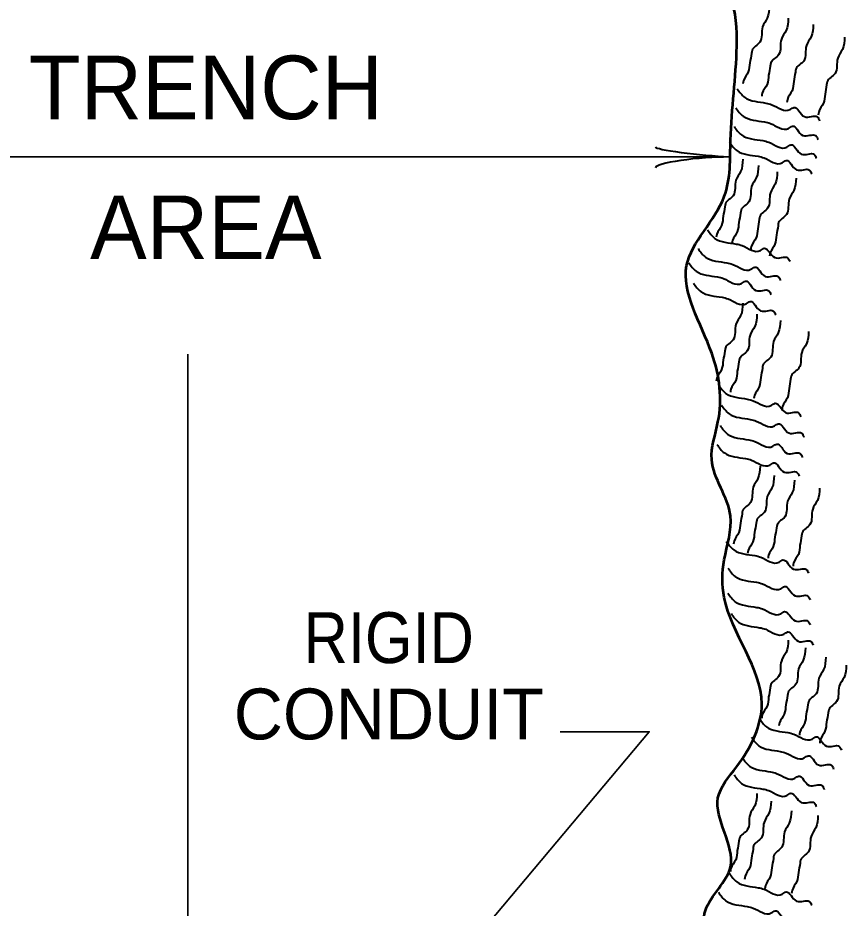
# Model space of a CAD drawing. Extents: x -488 to 193, y 19 to 459.
# Drawn here: x -199.42 to -166.87, y 242.11 to 277.11 of the extents above; entities that cross this region are included whole.
import ezdxf
from ezdxf.enums import TextEntityAlignment as Align

# ---------------------------------------------------------------- set-up
doc = ezdxf.new("R2010")
doc.units = 0
doc.header["$LTSCALE"] = 0.8
doc.layers.add('1', color=7, linetype='Continuous', lineweight=40)

msp = doc.modelspace()

# ---------------------------------------------------------------- linework, layer by layer
at = {"layer": '1', "lineweight": 35}
for p, q in [((-171.4865, 271.6481), (-212.2884, 271.6481)), ((-192.7425, 224.5147), (-192.7425, 263.8855))]:
    msp.add_line(p, q, dxfattribs=at)
msp.add_lwpolyline([(-187.0093, 234.2723), (-174.6099, 249.0493), (-178.1099, 249.0493)], dxfattribs=at)
at = {"layer": '1'}
for centre, major_axis, ratio, start_param, end_param in [((-172.607, 271.8597), (1.7565, -0.1757), 0.07063, 3.1407148, 5.41811), ((-172.5777, 271.3718), (1.7857, 0.1562), 0.122415, 0.8963533, 3.1415927)]:
    msp.add_ellipse(centre, major_axis=major_axis, ratio=ratio, start_param=start_param, end_param=end_param, dxfattribs=at)
at = {"layer": '1', "lineweight": 53}
msp.add_spline([(-212.7425, 318.8428), (-213.2734, 312.6869), (-212.2884, 310.2246), (-213.2734, 308.0085), (-212.5347, 306.0386), (-213.2734, 303.3301), (-212.2884, 301.6064), (-212.0422, 299.3903), (-212.2884, 295.943), (-212.5347, 294.2194), (-213.5196, 292.9882), (-213.7658, 292.2495), (-213.2734, 291.0183), (-213.0272, 289.5409), (-212.7809, 287.8173), (-212.5347, 286.0937), (-212.5347, 284.1237), (-211.5497, 281.4152), (-211.796, 279.6916), (-212.2884, 278.7066), (-212.2884, 275.9981), (-212.0422, 272.797), (-212.2884, 271.5658), (-212.2884, 268.8572), (-212.7809, 265.41), (-212.7809, 262.9477), (-213.7658, 259.7466), (-213.0272, 258.0229), (-213.2734, 255.8068), (-213.5196, 253.0982), (-213.2734, 251.3746), (-213.0272, 248.4198), (-212.7809, 246.6962), (-213.0272, 244.7263), (-213.0272, 241.5252), (-212.2884, 240.7866), (-212.7809, 236.8468), (-212.7809, 234.6307), (-212.5347, 233.1532), (-213.0272, 230.1985), (-212.5347, 228.9673), (-213.0272, 226.7512), (-212.5347, 225.7662), (-210.5648, 223.7964), (-208.8412, 224.2888), (-207.1175, 225.52), (-205.6401, 224.2888), (-204.1627, 224.0426), (-200.9617, 224.0426), (-197.7606, 225.2738), (-196.7757, 224.5351), (-192.5897, 224.5351), (-188.8962, 225.0276), (-186.9263, 224.5351), (-182.7403, 225.0276), (-181.2629, 224.7813), (-176.8307, 225.0276), (-176.3382, 224.2888), (-173.3834, 224.7813), (-171.1673, 227.7362), (-171.4136, 229.4597), (-171.6598, 230.4447), (-173.1372, 235.1232), (-171.1673, 238.3242), (-172.3985, 241.0327), (-172.3985, 242.0177), (-171.4136, 243.7413), (-171.906, 246.4499), (-171.1673, 247.6811), (-170.1824, 250.1434), (-171.6598, 254.3294), (-171.6598, 255.8068), (-171.4136, 257.5305), (-172.1522, 259.7466), (-171.906, 261.224), (-172.1522, 263.9326), (-173.1372, 267.3798), (-171.6598, 270.0884), (-171.4136, 272.3045), (-171.1673, 275.9981), (-171.4136, 277.9679), (-172.1522, 279.6916), (-172.1522, 281.169), (-171.906, 284.1237), (-172.891, 287.0786), (-173.1372, 289.7872), (-171.4136, 292.4957), (-172.1522, 294.4656), (-172.3985, 295.6968), (-171.1673, 298.6516), (-172.1522, 300.8677), (-172.1522, 305.0537), (-171.906, 306.5311), (-171.6598, 308.0085), (-172.6447, 310.7171), (-172.891, 312.1945), (-172.7425, 318.8428)], degree=3, dxfattribs=at)
at = {"layer": '1'}
for points in [[(-169.8844, 277.5847), (-169.9699, 277.0997), (-170.1552, 276.7574), (-170.2622, 276.1511), (-170.5689, 275.8302), (-170.5902, 275.709), (-170.6543, 275.3452), (-170.7184, 274.9814), (-170.9039, 274.6392), (-170.9253, 274.5178)], [(-169.1457, 277.0922), (-169.2312, 276.6073), (-169.4166, 276.265), (-169.5235, 275.6587), (-169.8303, 275.3377), (-169.8515, 275.2166), (-169.9157, 274.8528), (-169.9797, 274.489), (-170.1652, 274.1467), (-170.1867, 274.0254)], [(-168.1608, 276.846), (-168.2463, 276.3611), (-168.4316, 276.0188), (-168.5385, 275.4124), (-168.8452, 275.0915), (-168.8665, 274.9703), (-168.9307, 274.6065), (-168.9947, 274.2428), (-169.1803, 273.9005), (-169.2017, 273.7792)], [(-166.9296, 276.3535), (-167.0151, 275.8686), (-167.2004, 275.5263), (-167.3073, 274.9199), (-167.6141, 274.599), (-167.6353, 274.4778), (-167.6995, 274.114), (-167.7636, 273.7502), (-167.9491, 273.408), (-167.9705, 273.2867)], [(-171.1485, 274.3161), (-170.8556, 273.9825), (-170.0231, 273.7595), (-169.7852, 273.6958), (-169.0717, 273.5046), (-168.9209, 273.5917), (-168.5088, 273.2264), (-168.0014, 273.2177), (-167.9143, 273.0671)], [(-171.21, 273.5773), (-170.9171, 273.2437), (-170.0846, 273.0207), (-169.8467, 272.9571), (-169.1333, 272.7658), (-168.9824, 272.8529), (-168.5703, 272.4877), (-168.0629, 272.479), (-167.9758, 272.3283)], [(-171.2716, 272.8387), (-170.9787, 272.5051), (-170.1462, 272.2821), (-169.9083, 272.2184), (-169.1948, 272.0272), (-169.044, 272.1142), (-168.6319, 271.749), (-168.1245, 271.7403), (-168.0374, 271.5897)], [(-171.4562, 272.2231), (-171.1633, 271.8895), (-170.3308, 271.6665), (-170.093, 271.6028), (-169.3795, 271.4116), (-169.2287, 271.4987), (-168.8166, 271.1334), (-168.3092, 271.1248), (-168.2221, 270.9741)], [(-170.9309, 271.5519), (-171.0164, 271.067), (-171.2018, 270.7247), (-171.3087, 270.1183), (-171.6154, 269.7974), (-171.6367, 269.6762), (-171.7008, 269.3124), (-171.7649, 268.9487), (-171.9504, 268.6064), (-171.9718, 268.4851)], [(-170.3153, 271.3057), (-170.4008, 270.8208), (-170.5862, 270.4785), (-170.6931, 269.8722), (-170.9998, 269.5512), (-171.0211, 269.4301), (-171.0853, 269.0662), (-171.1493, 268.7025), (-171.3348, 268.3603), (-171.3562, 268.2389)], [(-169.5767, 271.0595), (-169.6622, 270.5746), (-169.8475, 270.2322), (-169.9544, 269.6259), (-170.2612, 269.305), (-170.2824, 269.1838), (-170.3466, 268.82), (-170.4107, 268.4563), (-170.5962, 268.114), (-170.6176, 267.9927)], [(-168.8379, 270.8132), (-168.9234, 270.3283), (-169.1087, 269.986), (-169.2157, 269.3797), (-169.5224, 269.0587), (-169.5437, 268.9376), (-169.6078, 268.5738), (-169.6719, 268.21), (-169.8574, 267.8678), (-169.8788, 267.7464)], [(-172.318, 268.7758), (-172.0251, 268.4423), (-171.1926, 268.2192), (-170.9547, 268.1556), (-170.2413, 267.9643), (-170.0904, 268.0514), (-169.6783, 267.6862), (-169.1709, 267.6775), (-169.0838, 267.5268)], [(-172.6873, 268.0371), (-172.3944, 267.7035), (-171.5619, 267.4805), (-171.3241, 267.4168), (-170.6106, 267.2256), (-170.4597, 267.3127), (-170.0477, 266.9474), (-169.5402, 266.9387), (-169.4532, 266.7881)], [(-173.0567, 267.4831), (-172.7637, 267.1495), (-171.9313, 266.9265), (-171.6934, 266.8628), (-170.9799, 266.6716), (-170.8291, 266.7587), (-170.417, 266.3934), (-169.9096, 266.3847), (-169.8225, 266.2341)], [(-172.872, 266.6828), (-172.5791, 266.3492), (-171.7466, 266.1262), (-171.5087, 266.0626), (-170.7952, 265.8713), (-170.6444, 265.9584), (-170.2323, 265.5932), (-169.7249, 265.5845), (-169.6378, 265.4338)], [(-170.931, 265.8886), (-171.0165, 265.4037), (-171.2018, 265.0613), (-171.3088, 264.455), (-171.6155, 264.1341), (-171.6368, 264.0129), (-171.7009, 263.6491), (-171.765, 263.2853), (-171.9505, 262.9431), (-171.9719, 262.8218)], [(-170.377, 265.4577), (-170.4625, 264.9728), (-170.6478, 264.6304), (-170.7548, 264.0241), (-171.0615, 263.7032), (-171.0828, 263.582), (-171.1469, 263.2182), (-171.211, 262.8544), (-171.3965, 262.5122), (-171.4179, 262.3908)], [(-169.4536, 265.2114), (-169.5391, 264.7265), (-169.7244, 264.3842), (-169.8313, 263.7778), (-170.1381, 263.4569), (-170.1593, 263.3358), (-170.2235, 262.9719), (-170.2876, 262.6082), (-170.4731, 262.2659), (-170.4945, 262.1446)], [(-168.3456, 264.7805), (-168.4311, 264.2956), (-168.6164, 263.9532), (-168.7233, 263.3469), (-169.0301, 263.026), (-169.0513, 262.9048), (-169.1155, 262.541), (-169.1796, 262.1773), (-169.3651, 261.835), (-169.3865, 261.7137)], [(-171.8872, 262.6815), (-171.5942, 262.3479), (-170.7618, 262.1249), (-170.5239, 262.0612), (-169.8104, 261.87), (-169.6596, 261.9571), (-169.2475, 261.5918), (-168.7401, 261.5832), (-168.653, 261.4325)], [(-171.764, 261.8812), (-171.4711, 261.5477), (-170.6386, 261.3247), (-170.4007, 261.261), (-169.6873, 261.0697), (-169.5364, 261.1568), (-169.1243, 260.7916), (-168.6169, 260.7829), (-168.5298, 260.6322)], [(-171.8256, 261.0809), (-171.5327, 260.7473), (-170.7002, 260.5243), (-170.4623, 260.4607), (-169.7488, 260.2694), (-169.598, 260.3565), (-169.1859, 259.9912), (-168.6785, 259.9826), (-168.5914, 259.8319)], [(-171.9487, 260.3422), (-171.6557, 260.0087), (-170.8233, 259.7857), (-170.5854, 259.722), (-169.8719, 259.5308), (-169.7211, 259.6178), (-169.309, 259.2526), (-168.8016, 259.2439), (-168.7145, 259.0933)], [(-170.2538, 259.4864), (-170.3393, 259.0015), (-170.5247, 258.6592), (-170.6316, 258.0528), (-170.9383, 257.7319), (-170.9596, 257.6107), (-171.0238, 257.2469), (-171.0878, 256.8832), (-171.2733, 256.5409), (-171.2947, 256.4196)], [(-169.6998, 259.1171), (-169.7853, 258.6322), (-169.9707, 258.2898), (-170.0776, 257.6835), (-170.3843, 257.3626), (-170.4056, 257.2414), (-170.4698, 256.8776), (-170.5338, 256.5138), (-170.7193, 256.1716), (-170.7407, 256.0503)], [(-168.8995, 258.9324), (-168.985, 258.4475), (-169.1703, 258.1052), (-169.2772, 257.4988), (-169.584, 257.1779), (-169.6052, 257.0567), (-169.6694, 256.6929), (-169.7335, 256.3292), (-169.919, 255.9869), (-169.9404, 255.8656)], [(-167.9146, 258.6246), (-168.0001, 258.1397), (-168.1854, 257.7973), (-168.2923, 257.191), (-168.5991, 256.8701), (-168.6203, 256.7489), (-168.6845, 256.3851), (-168.7486, 256.0213), (-168.9341, 255.6791), (-168.9555, 255.5577)], [(-171.5793, 256.5256), (-171.2864, 256.192), (-170.4539, 255.969), (-170.2161, 255.9053), (-169.5026, 255.7141), (-169.3517, 255.8012), (-168.9397, 255.4359), (-168.4322, 255.4272), (-168.3452, 255.2766)], [(-171.5178, 255.4791), (-171.2249, 255.1455), (-170.3924, 254.9225), (-170.1546, 254.8588), (-169.4411, 254.6676), (-169.2902, 254.7547), (-168.8782, 254.3894), (-168.3707, 254.3807), (-168.2837, 254.2301)], [(-171.5178, 254.4942), (-171.2249, 254.1606), (-170.3924, 253.9376), (-170.1546, 253.8739), (-169.4411, 253.6827), (-169.2902, 253.7697), (-168.8782, 253.4045), (-168.3707, 253.3958), (-168.2837, 253.2452)], [(-171.3947, 253.6939), (-171.1017, 253.3603), (-170.2692, 253.1373), (-170.0314, 253.0737), (-169.3179, 252.8824), (-169.1671, 252.9695), (-168.755, 252.6042), (-168.2476, 252.5956), (-168.1605, 252.4449)], [(-169.1457, 252.6534), (-169.2312, 252.1685), (-169.4166, 251.8262), (-169.5235, 251.2198), (-169.8303, 250.8989), (-169.8515, 250.7777), (-169.9157, 250.4139), (-169.9797, 250.0502), (-170.1652, 249.7079), (-170.1867, 249.5866)], [(-168.4686, 252.3457), (-168.5541, 251.8607), (-168.7394, 251.5184), (-168.8463, 250.9121), (-169.1531, 250.5912), (-169.1743, 250.47), (-169.2385, 250.1062), (-169.3026, 249.7424), (-169.4881, 249.4002), (-169.5095, 249.2788)], [(-167.6683, 251.9763), (-167.7538, 251.4914), (-167.9392, 251.1491), (-168.0461, 250.5427), (-168.3528, 250.2218), (-168.3741, 250.1007), (-168.4382, 249.7368), (-168.5023, 249.3731), (-168.6878, 249.0308), (-168.7092, 248.9095)], [(-166.8681, 251.6685), (-166.9536, 251.1836), (-167.1389, 250.8413), (-167.2458, 250.2349), (-167.5526, 249.914), (-167.5738, 249.7928), (-167.638, 249.429), (-167.7021, 249.0652), (-167.8876, 248.723), (-167.909, 248.6017)], [(-170.2867, 249.5695), (-169.9938, 249.2359), (-169.1612, 249.0129), (-168.9234, 248.9492), (-168.2099, 248.758), (-168.0591, 248.8451), (-167.647, 248.4798), (-167.1396, 248.4712), (-167.0525, 248.3205)], [(-170.5944, 248.8308), (-170.3015, 248.4972), (-169.469, 248.2742), (-169.2312, 248.2106), (-168.5177, 248.0193), (-168.3668, 248.1064), (-167.9547, 247.7412), (-167.4473, 247.7325), (-167.3603, 247.5818)], [(-170.9638, 248.0305), (-170.6708, 247.6969), (-169.8383, 247.4739), (-169.6005, 247.4102), (-168.887, 247.219), (-168.7362, 247.3061), (-168.3241, 246.9408), (-167.8167, 246.9322), (-167.7296, 246.7815)], [(-171.2716, 247.3534), (-170.9787, 247.0198), (-170.1462, 246.7968), (-169.9083, 246.7332), (-169.1948, 246.5419), (-169.044, 246.629), (-168.6319, 246.2637), (-168.1245, 246.2551), (-168.0374, 246.1044)], [(-170.3768, 246.6206), (-170.4623, 246.1357), (-170.6477, 245.7933), (-170.7546, 245.187), (-171.0613, 244.8661), (-171.0826, 244.7449), (-171.1467, 244.3811), (-171.2108, 244.0173), (-171.3963, 243.6751), (-171.4177, 243.5537)], [(-169.8228, 246.3128), (-169.9083, 245.8279), (-170.0937, 245.4856), (-170.2006, 244.8792), (-170.5073, 244.5583), (-170.5286, 244.4372), (-170.5927, 244.0733), (-170.6568, 243.7096), (-170.8423, 243.3673), (-170.8637, 243.246)], [(-169.0226, 245.9434), (-169.1081, 245.4585), (-169.2934, 245.1162), (-169.4003, 244.5098), (-169.7071, 244.1889), (-169.7283, 244.0677), (-169.7925, 243.7039), (-169.8566, 243.3402), (-170.0421, 242.9979), (-170.0635, 242.8766)], [(-167.9761, 245.7587), (-168.0616, 245.2738), (-168.2469, 244.9315), (-168.3538, 244.3252), (-168.6606, 244.0042), (-168.6818, 243.8831), (-168.746, 243.5192), (-168.8101, 243.1555), (-168.9956, 242.8132), (-169.017, 242.6919)], [(-171.4562, 243.4752), (-171.1633, 243.1416), (-170.3307, 242.9186), (-170.0929, 242.8549), (-169.3794, 242.6637), (-169.2286, 242.7507), (-168.8165, 242.3855), (-168.3091, 242.3768), (-168.222, 242.2262)], [(-171.8871, 242.7365), (-171.5942, 242.4029), (-170.7617, 242.1799), (-170.5238, 242.1162), (-169.8103, 241.925), (-169.6595, 242.0121), (-169.2474, 241.6468), (-168.74, 241.6382), (-168.6529, 241.4875)]]:
    msp.add_spline(points, degree=3, dxfattribs=at)

# ---------------------------------------------------------------- texts
for s, height, p in [('TRENCH', 2.5, (-192.033, 273.1247)), ('AREA', 2.5, (-192.0329, 267.6247)), ('CONDUIT', 2, (-184.8443, 248.7461))]:
    msp.add_text(s, height=height, dxfattribs=at).set_placement(p, align=Align.CENTER)
at = {"layer": '1', "width": 0.9}
msp.add_text('RIGID', height=2, dxfattribs=at).set_placement((-184.8443, 251.7461), align=Align.CENTER)

doc.saveas('drawing.dxf')
